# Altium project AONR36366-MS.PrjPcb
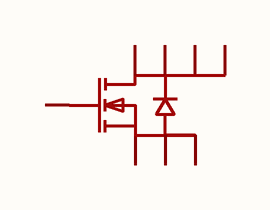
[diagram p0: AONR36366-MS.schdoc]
1 sheet, 1 parts. Net scope: global (net labels, ports and power ports of the same name join across sheets).

## Sheet AONR36366-MS.schdoc
size 127 x 101 mm

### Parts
Q?  aonr36366-ms  [POWERVDFN-8_L3.2-W3.1-P0.65-LS3.3-BL-2]  (value not drawn)

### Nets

Not connected (* = marked no-connect by the designer): Q? 1(S) 2(S) 3(S) 4(G) 5(D) 6(D) 7(D) 8(D)

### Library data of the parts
Q? = aonr36366-ms: 数量:1个N沟道;漏源电压(Vdss):30V;连续漏极电流(Id):100A;导通电阻(RDS(on)):6mΩ@4.5V;耗散功率(Pd):62.5W;阈值电压(Vgs(th)):2.5V;; Manufacturer: MSKSEMI(美森科); AddInBom: yes; Number: 1个N沟道; Drain to Source Voltage: 30V; Current - Continuous Drain(Id): 100A; Pd - Power Dissipation: 62.5W; Gate Threshold Voltage (Vgs(th)): 2.5V; Gate Charge(Qg): 31.6nC@4.5V; Input Capacitance(Ciss): 3.075nF; Reverse Transfer Capacitance (Crss@Vds): 315pF; Type: N沟道; Output Capacitance(Coss): 400pF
